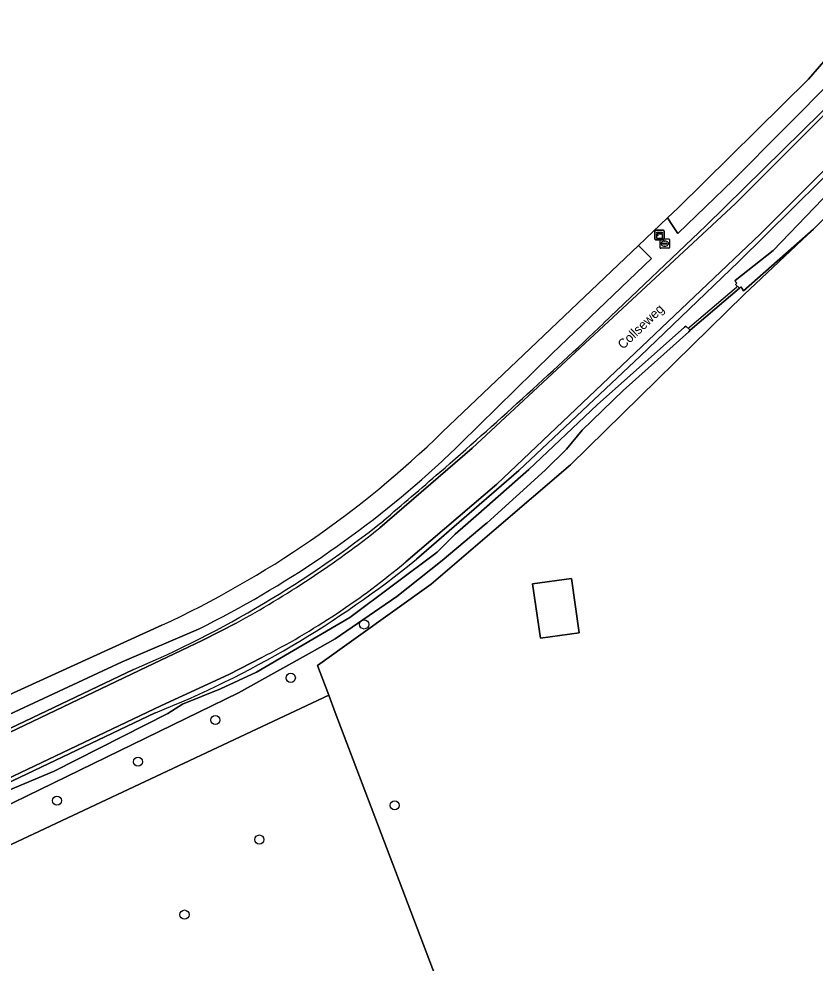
# Model space of a CAD drawing. Extents: x 164494 to 166241, y 382475 to 384495.
# Drawn here: x 165112.8 to 165197.8, y 383771 to 383871.8 of the extents above; entities that cross this region are included whole.
import ezdxf

# ---------------------------------------------------------------- set-up
doc = ezdxf.new("R2010")
doc.units = 0
for name, color, linetype in [('IMGEO_Berm_halfverhard', 7, 'Continuous'), ('IMGEO_Boom', 7, 'Continuous'), ('IMGEO_Bouwland', 7, 'Continuous'), ('IMGEO_Duiker', 7, 'Continuous'), ('IMGEO_Erf', 7, 'Continuous'), ('IMGEO_Groenvoorziening', 7, 'Continuous'), ('IMGEO_Kast', 7, 'Continuous'), ('IMGEO_Openbare_ruimte_label', 7, 'Continuous'), ('IMGEO_Pand', 7, 'Continuous'), ('IMGEO_Rijbaan_lokaal_gesloten', 7, 'Continuous'), ('IMGEO_Rioolput', 7, 'Continuous'), ('IMGEO_Waterloop', 7, 'Continuous')]:
    doc.layers.add(name, color=color, linetype=linetype)

msp = doc.modelspace()

# ---------------------------------------------------------------- linework, layer by layer
at = {"layer": 'IMGEO_Berm_halfverhard'}
for points in [[(165151.31, 383817.47), (165161.16, 383825.98), (165189.28, 383852.13), (165204.49, 383867.34)], [(165209.76, 383866.98), (165207.1, 383864.05), (165191.89, 383848.84), (165163.79, 383822.15), (165154.07, 383813.85)], [(165155.21, 383814.13), (165161.39, 383819.48), (165166.15, 383823.61), (165179.1, 383835.82), (165189.6, 383845.87), (165204.16, 383860.28), (165210.96, 383867.3)], [(165200.47, 383863.87), (165186.12, 383849.72), (165175.19, 383839.32)], [(165125.01, 383802.35), (165070.9, 383776.54), (165070.84, 383776.64), (165070.12, 383776.3), (165070.35, 383775.84), (165125.61, 383802.24), (165132.42, 383805.48), (165135.98, 383807.3)], [(165138.71, 383803.64), (165135.2, 383801.82), (165128.02, 383798.5), (165072.24, 383771.98), (165072.32, 383771.84), (165072.47, 383771.52), (165073.32, 383771.92), (165073.3, 383772.01), (165127.34, 383797.73)]]:
    msp.add_lwpolyline(points, dxfattribs=at)
for centre, radius, start, end in [((164779.69, 384256.64), 574.96, 311.10726, 313.46198), ((164761.97, 384277.25), 602.13, 310.33243, 311.08901), ((165079.94, 383908.37), 115.2, 293.032, 308.5215), ((165081.75, 383905.66), 112.32, 298.8689, 308.266), ((165087.22, 383897.79), 107.81, 291.8507, 309.1027), ((165100.71, 383877.51), 83.07, 297.2226, 309.9697)]:
    msp.add_arc(centre, radius, start, end, dxfattribs=at)
at = {"layer": 'IMGEO_Boom'}
for centre in [(165149.64, 383807.17), (165141.8, 383801.47), (165133.74, 383796.96), (165125.5, 383792.51), (165116.84, 383788.36), (165152.89, 383787.85), (165138.45, 383784.2), (165130.46, 383776.19)]:
    msp.add_circle(centre, 0.489, dxfattribs=at)
at = {"layer": 'IMGEO_Bouwland'}
for points in [[(165158.01, 383827.73), (165178.91, 383847.63), (165182.01, 383850.58), (165183.14, 383851.66), (165197.08, 383865.4), (165202.22, 383871.34), (165210.02, 383881.29), (165214.6, 383887.84), (165221.57, 383898.87), (165232.71, 383917.65), (165253.51, 383950.72), (165257.18, 383956.47), (165255.58, 383956.1), (165245.66, 383954.08), (165196.93, 383941.72), (165196.92, 383941.72), (165158.09, 383932.3), (165144.84, 383929.35), (165142.48, 383930.92), (165138.05, 383949.06), (165081.65, 383927.93)], [(165013.29, 383752.46), (165013.04, 383753), (165013.89, 383753.35), (165017.96, 383755.36), (165010.92, 383775.15), (164984.51, 383842.14), (165024.56, 383854.95), (165047.06, 383769.21), (165048.94, 383770.11), (165063.29, 383777.17), (165068.85, 383779.89), (165101.95, 383795.22), (165128.04, 383807.08)], [(165205.03, 383703.32), (165208.3, 383727.11), (165207.26, 383727.36), (165189.95, 383730.66), (165170.64, 383734.86), (165157.89, 383767.91), (165146.55, 383797.78), (165145.85, 383799.61), (165106.62, 383781.19), (165067, 383763.68), (165014.17, 383738.3), (165018.06, 383725.95), (164998.2, 383721.96), (164999.29, 383719.09), (165027.4, 383643.26)]]:
    msp.add_lwpolyline(points, dxfattribs=at)
msp.add_arc((165082.64, 383905.02), 107.95, 294.8695, 314.2758, dxfattribs=at)
at = {"layer": 'IMGEO_Duiker'}
msp.add_lwpolyline([(165184.22, 383838.79), (165184.39, 383838.94), (165189.37, 383843.18), (165189.48, 383843.28)], dxfattribs=at)
at = {"layer": 'IMGEO_Erf'}
msp.add_lwpolyline([(165216.67, 383868.52), (165215.46, 383867.31), (165214.25, 383865.78), (165197.6, 383849.39), (165190.2, 383842.41), (165171.67, 383824.21), (165163.5, 383817.22), (165156.8, 383811.47), (165144.65, 383802.77), (165145.85, 383799.61), (165146.55, 383797.78), (165157.89, 383767.91), (165170.64, 383734.86), (165189.95, 383730.66), (165207.26, 383727.36), (165211.82, 383750), (165222.05, 383798.74), (165224.17, 383798.09), (165224.48, 383798.05), (165224.58, 383798.72), (165221.74, 383801.03)], dxfattribs=at)
msp.add_lwpolyline([(165168.47, 383805.69), (165167.62, 383811.49), (165171.75, 383812.09), (165172.6, 383806.29)], close=True, dxfattribs=at)
at = {"layer": 'IMGEO_Groenvoorziening'}
for points in [[(165258.85, 383956.81), (165258.57, 383956.78), (165257.18, 383956.47), (165253.51, 383950.72), (165254.42, 383950.13), (165255.25, 383949.6), (165245.53, 383934.16), (165236.56, 383918.92), (165232.41, 383912.89), (165223.55, 383898.77), (165210.14, 383878.39), (165203.98, 383870.35), (165199.84, 383865.48), (165189.04, 383854.61), (165183.1, 383848.91), (165182.55, 383849.75), (165182.01, 383850.58), (165178.91, 383847.63), (165179.62, 383846.93), (165180.32, 383846.24), (165169.72, 383836.09), (165159.93, 383826.48)], [(165215.8, 383871.33), (165215.83, 383871.02), (165210.96, 383867.3), (165204.16, 383860.28), (165189.6, 383845.87), (165179.1, 383835.82), (165166.15, 383823.61), (165161.39, 383819.48), (165155.21, 383814.13)], [(165175.19, 383839.32), (165186.12, 383849.72), (165200.47, 383863.87)], [(165110.23, 383788.86), (165116.54, 383791.5), (165128.67, 383797.67), (165130.26, 383798.64), (165134.29, 383800.29), (165138.15, 383802.07), (165148.11, 383807.92), (165157.42, 383814.89), (165159.34, 383816.8), (165161.85, 383818.99), (165167.23, 383823.72), (165174.5, 383830.61), (165183.84, 383838.92), (165183.98, 383839.03), (165184.43, 383838.59), (165189.69, 383843.07), (165189.29, 383843.47), (165189.41, 383843.62), (165189.29, 383843.74), (165189.22, 383843.89), (165193.29, 383847.1), (165202.07, 383856.24)], [(165106.62, 383781.19), (165145.85, 383799.61), (165144.65, 383802.77), (165156.8, 383811.47), (165163.5, 383817.22), (165171.67, 383824.21), (165190.2, 383842.41), (165197.6, 383849.39), (165190.11, 383842.8), (165189.95, 383843.06), (165189.85, 383843.21), (165189.69, 383843.07), (165184.43, 383838.59), (165184.29, 383838.42), (165177.29, 383832.16), (165172.9, 383827.92), (165171.25, 383825.9), (165168.95, 383823.63), (165162.75, 383818.03), (165162.65, 383817.94), (165157.96, 383813.99), (165153.11, 383810.16), (165146.53, 383805.62), (165144.08, 383804.26), (165136.21, 383799.88), (165106.54, 383785.41)], [(165131.96, 383806.67), (165123.79, 383803.17), (165069.86, 383778.04), (165069.54, 383778.63), (165069.4, 383778.89), (165068.85, 383779.89), (165063.29, 383777.17), (165063.94, 383776.01), (165064.3, 383775.36), (165019.47, 383753.93), (165019.08, 383754.67), (165018.58, 383755.66), (165017.96, 383755.36), (165013.89, 383753.35), (165013.04, 383753), (165013.29, 383752.46)], [(165029.82, 383757), (165052.87, 383767.96), (165052.82, 383768.03), (165053.64, 383768.42), (165070.12, 383776.3), (165070.84, 383776.64), (165070.9, 383776.54), (165125.01, 383802.35)], [(165127.34, 383797.73), (165073.3, 383772.01), (165073.32, 383771.92), (165072.47, 383771.52), (165056.01, 383763.59), (165055.21, 383763.21), (165055.14, 383763.3), (165032.08, 383752.25)]]:
    msp.add_lwpolyline(points, dxfattribs=at)
for centre, radius, start, end in [((164779.69, 384256.64), 574.96, 311.10726, 313.46198), ((165084.52, 383904.02), 108.16, 312.2371, 314.2028), ((165082.34, 383906.36), 111.36, 296.4621, 312.2597), ((164761.97, 384277.25), 602.13, 310.33243, 311.08901), ((165079.94, 383908.37), 115.2, 293.032, 308.5215), ((165087.22, 383897.79), 107.81, 291.8507, 309.1027)]:
    msp.add_arc(centre, radius, start, end, dxfattribs=at)
at = {"layer": 'IMGEO_Kast'}
for p, q in [((165180.67, 383848.32), (165180.67, 383849.16)), ((165180.67, 383849.16), (165180.67, 383848.32)), ((165180.74, 383849.25), (165181.58, 383849.25)), ((165181.58, 383849.25), (165180.74, 383849.25)), ((165181.66, 383849.17), (165181.66, 383848.33)), ((165181.66, 383848.33), (165181.66, 383849.17)), ((165181.59, 383848.25), (165180.75, 383848.25)), ((165180.75, 383848.25), (165181.59, 383848.25))]:
    msp.add_line(p, q, dxfattribs=at)
for points in [[(165180.86, 383849.04), (165181.46, 383849.04), (165181.46, 383848.95), (165180.86, 383848.95), (165180.86, 383849.04)], [(165180.86, 383848.86), (165181.46, 383848.86), (165181.46, 383848.38), (165180.86, 383848.38), (165180.86, 383848.86)]]:
    msp.add_lwpolyline(points, dxfattribs=at)
msp.add_circle((165180.94, 383848.71), 0.0377, dxfattribs=at)
for centre, start, end in [((165180.74, 383849.17), 92.4484, 184.2845), ((165180.74, 383849.17), 92.4484, 184.2845), ((165181.59, 383849.17), 2.4484, 94.2845), ((165181.59, 383849.17), 2.4484, 94.2845), ((165180.74, 383848.33), 182.4484, 274.2845), ((165180.74, 383848.33), 182.4484, 274.2845), ((165181.59, 383848.33), 272.4484, 4.2845), ((165181.59, 383848.33), 272.4484, 4.2845)]:
    msp.add_arc(centre, 0.0779, start, end, dxfattribs=at)
at = {"layer": 'IMGEO_Pand'}
msp.add_lwpolyline([(165168.47, 383805.69), (165172.6, 383806.29), (165171.75, 383812.09), (165167.62, 383811.49)], close=True, dxfattribs=at)
at = {"layer": 'IMGEO_Rijbaan_lokaal_gesloten'}
for points in [[(165204.49, 383867.34), (165189.28, 383852.13), (165161.16, 383825.98), (165151.31, 383817.47)], [(165154.07, 383813.85), (165163.79, 383822.15), (165191.89, 383848.84), (165207.1, 383864.05), (165209.76, 383866.98)], [(165135.98, 383807.3), (165132.42, 383805.48), (165125.61, 383802.24), (165070.35, 383775.84), (165070.36, 383775.82), (165072.24, 383771.98), (165128.02, 383798.5), (165135.2, 383801.82), (165138.71, 383803.64)]]:
    msp.add_lwpolyline(points, dxfattribs=at)
for centre, radius, start, end in [((165081.75, 383905.66), 112.32, 298.8689, 308.266), ((165100.71, 383877.51), 83.07, 297.2226, 309.9697)]:
    msp.add_arc(centre, radius, start, end, dxfattribs=at)
at = {"layer": 'IMGEO_Rioolput'}
for p, q in [((165181.22, 383847.41), (165181.22, 383848.26)), ((165181.29, 383848.33), (165182.15, 383848.33)), ((165181.48, 383847.83), (165181.48, 383847.84)), ((165181.52, 383847.88), (165181.92, 383847.88)), ((165181.91, 383847.79), (165181.52, 383847.79)), ((165181.71, 383848.11), (165181.73, 383848.11)), ((165181.96, 383847.84), (165181.96, 383847.83)), ((165182.22, 383848.26), (165182.22, 383847.41)), ((165182.15, 383847.33), (165181.29, 383847.33)), ((165181.73, 383847.55), (165181.7, 383847.55))]:
    msp.add_line(p, q, dxfattribs=at)
for points in [[(165181.22, 383847.41), (165181.22, 383848.26)], [(165181.29, 383848.33), (165182.15, 383848.33)], [(165182.22, 383848.26), (165182.22, 383847.41)], [(165182.15, 383847.33), (165181.29, 383847.33)]]:
    msp.add_lwpolyline(points, dxfattribs=at)
for centre, radius, start, end in [((165181.29, 383848.26), 0.0765, 91.552, 178.448), ((165181.29, 383848.26), 0.0765, 91.552, 178.448), ((165181.52, 383847.84), 0.0403, 85.8775, 175.7526), ((165181.51, 383847.83), 0.0366, 178.938, 274.7102), ((165181.92, 383847.83), 0.043, 264.8664, 352.4533), ((165181.92, 383847.84), 0.0386, 1.7309, 96.639), ((165182.14, 383848.26), 0.0765, 1.552, 88.448), ((165182.14, 383848.26), 0.0765, 1.552, 88.448), ((165181.29, 383847.41), 0.0765, 181.552, 268.448), ((165181.29, 383847.41), 0.0765, 181.552, 268.448), ((165182.14, 383847.41), 0.0765, 271.552, 358.448), ((165182.14, 383847.41), 0.0765, 271.552, 358.448)]:
    msp.add_arc(centre, radius, start, end, dxfattribs=at)
for centre, major_axis, ratio, start_param, end_param in [((165181.71, 383847.83), (-0.387, 0.002), 0.722429, 4.712389, 7.853982), ((165181.73, 383847.83), (-0.39, 0.002), 0.717154, 1.570796, 4.712389)]:
    msp.add_ellipse(centre, major_axis=major_axis, ratio=ratio, start_param=start_param, end_param=end_param, dxfattribs=at)
at = {"layer": 'IMGEO_Waterloop'}
msp.add_lwpolyline([(165245.53, 383934.16), (165255.25, 383949.6), (165254.42, 383950.13), (165253.51, 383950.72), (165232.71, 383917.65), (165221.57, 383898.87), (165214.6, 383887.84), (165210.02, 383881.29), (165202.22, 383871.34), (165197.08, 383865.4), (165183.14, 383851.66), (165182.01, 383850.58), (165182.55, 383849.75), (165183.1, 383848.91), (165189.04, 383854.61), (165199.84, 383865.48), (165203.98, 383870.35), (165210.14, 383878.39), (165223.55, 383898.77), (165232.41, 383912.89), (165236.56, 383918.92)], close=True, dxfattribs=at)
for points in [[(165215.94, 383869.99), (165213.36, 383867.78), (165208.44, 383862.32), (165202.07, 383856.24), (165193.29, 383847.1), (165189.22, 383843.89), (165189.29, 383843.74), (165189.41, 383843.62), (165189.29, 383843.47), (165189.69, 383843.07), (165189.85, 383843.21), (165189.95, 383843.06), (165190.11, 383842.8), (165197.6, 383849.39), (165214.25, 383865.78), (165215.46, 383867.31), (165216.67, 383868.52)], [(165159.93, 383826.48), (165169.72, 383836.09), (165180.32, 383846.24), (165179.62, 383846.93), (165178.91, 383847.63), (165158.01, 383827.73)], [(165106.54, 383785.41), (165136.21, 383799.88), (165144.08, 383804.26), (165146.53, 383805.62), (165153.11, 383810.16), (165157.96, 383813.99), (165162.65, 383817.94), (165162.75, 383818.03), (165168.95, 383823.63), (165171.25, 383825.9), (165172.9, 383827.92), (165177.29, 383832.16), (165184.29, 383838.42), (165184.43, 383838.59), (165183.98, 383839.03), (165183.84, 383838.92), (165174.5, 383830.61), (165167.23, 383823.72), (165161.85, 383818.99), (165159.34, 383816.8), (165157.42, 383814.89), (165148.11, 383807.92), (165138.15, 383802.07), (165134.29, 383800.29), (165130.26, 383798.64), (165128.67, 383797.67), (165116.54, 383791.5), (165110.23, 383788.86)], [(165128.04, 383807.08), (165101.95, 383795.22), (165068.85, 383779.89), (165069.4, 383778.89), (165069.54, 383778.63), (165069.86, 383778.04), (165123.79, 383803.17)], [(165123.79, 383803.17), (165131.96, 383806.67)]]:
    msp.add_lwpolyline(points, dxfattribs=at)
for centre, radius, start, end in [((165082.64, 383905.02), 107.95, 294.8695, 314.2758), ((165084.52, 383904.02), 108.16, 312.2371, 314.2028), ((165082.34, 383906.36), 111.36, 296.4621, 312.2597)]:
    msp.add_arc(centre, radius, start, end, dxfattribs=at)

# ---------------------------------------------------------------- texts
at = {"layer": 'IMGEO_Openbare_ruimte_label'}
msp.add_text('Collseweg', height=1, rotation=43.6226, dxfattribs=at).set_placement((165177.27, 383836.49))

doc.saveas('drawing.dxf')
